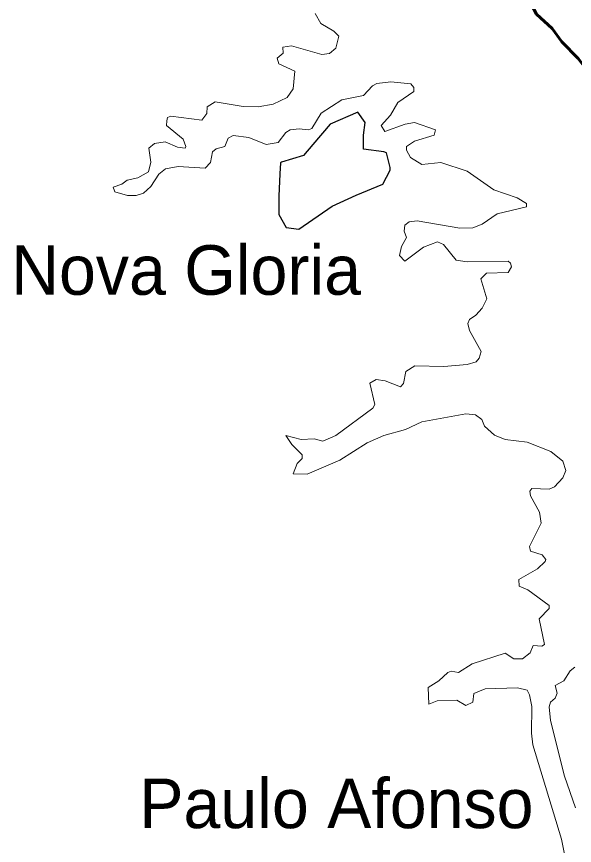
# Model space of a CAD drawing. Extents: x 553962 to 842807, y 8883888 to 9032388.
# Drawn here: x 578481 to 584109, y 8960294 to 8968659 of the extents above; entities that cross this region are included whole.
import ezdxf
from ezdxf.enums import TextEntityAlignment as Align

# ---------------------------------------------------------------- set-up
doc = ezdxf.new("R2010")
doc.units = 0
doc.header["$LTSCALE"] = 200
doc.linetypes.add('LONG_DASH_SHORT_DASH', pattern=[9.9, 6, -1.2, 1.5, -1.2])
for name, color, linetype, lineweight in [('21', 7, 'Continuous', 25), ('25', 7, 'Continuous', 13), ('41', 7, 'Continuous', 40), ('7', 7, 'LONG_DASH_SHORT_DASH', 60)]:
    doc.layers.add(name, color=color, linetype=linetype, lineweight=lineweight)

msp = doc.modelspace()

# ---------------------------------------------------------------- linework, layer by layer
at = {"layer": '21'}
msp.add_lwpolyline([(581144.7, 8967182.6), (581135.4, 8967071.1), (581126.2, 8966848.2), (581126.2, 8966662.4), (581200.4, 8966532.3), (581330.4, 8966513.8), (581664.7, 8966746), (581906.1, 8966857.5), (582175.4, 8966968.9), (582249.7, 8967108.2), (582249.7, 8967136.1), (582212.6, 8967284.7), (582184.7, 8967294), (581980.4, 8967321.9), (581980.4, 8967461.2), (581999, 8967591.2), (581924.7, 8967693.4), (581646.1, 8967572.7), (581469.7, 8967368.3), (581376.9, 8967256.9), (581154, 8967191.8)], close=True, dxfattribs=at)
at = {"layer": '25'}
msp.add_line((579471.8, 8966890.6), (579467.6, 8966902.2), dxfattribs=at)
msp.add_line((579471.8, 8966890.6), (579467.6, 8966902.2), dxfattribs=at)
for points in [[(579997.9, 8967607), (580002.2, 8967641.4), (580036, 8967653.3), (580349.3, 8967615), (580399.9, 8967680.5), (580404.5, 8967748.8), (580485.3, 8967797.5), (580765.4, 8967750.9), (580918.4, 8967748.8), (581071.3, 8967774.2), (581209.4, 8967844.3), (581273.1, 8967931.4), (581290, 8968109.6), (581126.5, 8968182.3), (581109.5, 8968238.9), (581170.9, 8968290.2), (581167, 8968349.8), (581254, 8968362.6), (581560.2, 8968277.7), (581636.5, 8968288.5), (581702.2, 8968341.5), (581733.9, 8968462.6), (581683.1, 8968511.3), (581551.5, 8968590), (581492, 8968691.9)], [(579997.9, 8967607), (580002.2, 8967641.4), (580036, 8967653.3), (580349.3, 8967615), (580399.9, 8967680.5), (580404.5, 8967748.8), (580485.3, 8967797.5), (580765.4, 8967750.9), (580918.4, 8967748.8), (581071.3, 8967774.2), (581209.4, 8967844.3), (581273.1, 8967931.4), (581290, 8968109.6), (581126.5, 8968182.3), (581109.5, 8968238.9), (581170.9, 8968290.2), (581167, 8968349.8), (581254, 8968362.6), (581560.2, 8968277.7), (581636.5, 8968288.5), (581702.2, 8968341.5), (581733.9, 8968462.6), (581683.1, 8968511.3), (581551.5, 8968590), (581492, 8968691.9)], [(581209.9, 8964412.9), (581198.1, 8964430.9), (581351.7, 8964392.4), (581483.4, 8964396.6), (581572.4, 8964375.4), (581702.2, 8964430.7), (582073.9, 8964708.9), (582095.1, 8964745.1), (582044.3, 8964959.3), (582107.7, 8964995.5), (582107.7, 8964995.5), (582201.2, 8964983), (582356.2, 8964921.4), (582384.1, 8964957.7), (582407.6, 8965076.4), (582498.3, 8965133.6), (582792, 8965127.4), (583025.6, 8965146.5), (583119.2, 8965176.5), (583148.8, 8965212.4), (583170, 8965280.6), (583051.2, 8965492.5), (583034.2, 8965562.9), (583049.1, 8965601.1), (583114.8, 8965645.7), (583178, 8965717.2), (583225.2, 8965811.2), (583165.9, 8966013.2), (583223.5, 8966068.5), (583441.9, 8966077), (583475.9, 8966134.3), (583465.2, 8966170.4), (583439.6, 8966189.4), (583025.6, 8966183.2), (582915.7, 8966200), (582789.8, 8966359.4), (582728.2, 8966384.9), (582588.1, 8966331.8), (582396.7, 8966191.8), (582346, 8966247.1), (582364.9, 8966338), (582415.8, 8966429.6), (582390.2, 8966492.9), (582396.9, 8966552.7), (582441.5, 8966588.8), (582524.1, 8966597.4), (582953.4, 8966525.2), (583085.1, 8966527.3), (583178.8, 8966563.5), (583331.5, 8966667.5), (583624.5, 8966739.8), (583624.6, 8966771.3), (583531.2, 8966831), (583297.3, 8966909.8), (583025.6, 8967098.7), (582760.3, 8967185.7), (582571.1, 8967166.8), (582456.7, 8967236.5), (582416, 8967311.4), (582416.1, 8967347.1), (582494.8, 8967400.4), (582694, 8967461.9), (582706.9, 8967517.1), (582494.3, 8967589.4), (582401.1, 8967574.5), (582195.1, 8967498.2), (582159.1, 8967561.8), (582254.4, 8967663.6), (582326.8, 8967791.2), (582488.1, 8967904.1), (582488.1, 8967944.1), (582458.3, 8967980.2), (582256.4, 8967999.4), (582116.5, 8967984.5), (582071.9, 8967959), (581982.3, 8967861.3), (581763.8, 8967818.8), (581553.6, 8967684.9), (581459.8, 8967529.9), (581427.3, 8967517.2), (581332, 8967527.8), (581241.1, 8967517), (581198.8, 8967489.5), (581119.9, 8967389.7), (580998.9, 8967368.6), (580825.2, 8967438.5), (580667.5, 8967459.7), (580614.4, 8967431.8), (580582.4, 8967349.3), (580493.6, 8967323.8), (580457.7, 8967294.3), (580438.2, 8967185.8), (580385.3, 8967130.7), (580111.4, 8967147.6), (579983.5, 8967124), (579915.9, 8967069.1), (579835, 8966943.6), (579762.8, 8966875.7), (579686.3, 8966854.5), (579601.1, 8966852.3), (579471.8, 8966890.6)], [(581209.9, 8964412.9), (581198.1, 8964430.9), (581351.7, 8964392.4), (581483.4, 8964396.6), (581572.4, 8964375.4), (581702.2, 8964430.7), (582073.9, 8964708.9), (582095.1, 8964745.1), (582044.3, 8964959.3), (582107.7, 8964995.5), (582107.7, 8964995.5), (582201.2, 8964983), (582356.2, 8964921.4), (582384.1, 8964957.7), (582407.6, 8965076.4), (582498.3, 8965133.6), (582792, 8965127.4), (583025.6, 8965146.5), (583119.2, 8965176.5), (583148.8, 8965212.4), (583170, 8965280.6), (583051.2, 8965492.5), (583034.2, 8965562.9), (583049.1, 8965601.1), (583114.8, 8965645.7), (583178, 8965717.2), (583225.2, 8965811.2), (583165.9, 8966013.2), (583223.5, 8966068.5), (583441.9, 8966077), (583475.9, 8966134.3), (583465.2, 8966170.4), (583439.6, 8966189.4), (583025.6, 8966183.2), (582915.7, 8966200), (582789.8, 8966359.4), (582728.2, 8966384.9), (582588.1, 8966331.8), (582396.7, 8966191.8), (582346, 8966247.1), (582364.9, 8966338), (582415.8, 8966429.6), (582390.2, 8966492.9), (582396.9, 8966552.7), (582441.5, 8966588.8), (582524.1, 8966597.4), (582953.4, 8966525.2), (583085.1, 8966527.3), (583178.8, 8966563.5), (583331.5, 8966667.5), (583624.5, 8966739.8), (583624.6, 8966771.3), (583531.2, 8966831), (583297.3, 8966909.8), (583025.6, 8967098.7), (582760.3, 8967185.7), (582571.1, 8967166.8), (582456.7, 8967236.5), (582416, 8967311.4), (582416.1, 8967347.1), (582494.8, 8967400.4), (582694, 8967461.9), (582706.9, 8967517.1), (582494.3, 8967589.4), (582401.1, 8967574.5), (582195.1, 8967498.2), (582159.1, 8967561.8), (582254.4, 8967663.6), (582326.8, 8967791.2), (582488.1, 8967904.1), (582488.1, 8967944.1), (582458.3, 8967980.2), (582256.4, 8967999.4), (582116.5, 8967984.5), (582071.9, 8967959), (581982.3, 8967861.3), (581763.8, 8967818.8), (581553.6, 8967684.9), (581459.8, 8967529.9), (581427.3, 8967517.2), (581332, 8967527.8), (581241.1, 8967517), (581198.8, 8967489.5), (581119.9, 8967389.7), (580998.9, 8967368.6), (580825.2, 8967438.5), (580667.5, 8967459.7), (580614.4, 8967431.8), (580582.4, 8967349.3), (580493.6, 8967323.8), (580457.7, 8967294.3), (580438.2, 8967185.8), (580385.3, 8967130.7), (580111.4, 8967147.6), (579983.5, 8967124), (579915.9, 8967069.1), (579835, 8966943.6), (579762.8, 8966875.7), (579686.3, 8966854.5), (579601.1, 8966852.3), (579471.8, 8966890.6)], [(579467.6, 8966902.2), (579455.3, 8966936.2), (579541.6, 8966967.5), (579595, 8967007.3), (579704, 8967033.2), (579811.7, 8967092.6), (579835, 8967188.5), (579813.9, 8967330.2), (579873.1, 8967378.9), (579979.2, 8967396.1), (580105, 8967343), (580105, 8967343), (580181.1, 8967330.4), (580187.4, 8967349.7), (580161, 8967421.7), (579992.3, 8967561.8), (579997.9, 8967607)], [(579467.6, 8966902.2), (579455.3, 8966936.2), (579541.6, 8966967.5), (579595, 8967007.3), (579704, 8967033.2), (579811.7, 8967092.6), (579835, 8967188.5), (579813.9, 8967330.2), (579873.1, 8967378.9), (579979.2, 8967396.1), (580105, 8967343), (580105, 8967343), (580181.1, 8967330.4), (580187.4, 8967349.7), (580161, 8967421.7), (579992.3, 8967561.8), (579997.9, 8967607)], [(583013.2, 8964651.5), (582571.3, 8964568.8), (582405.6, 8964492.4), (582184.7, 8964432.8), (582018.8, 8964356.3), (581742.6, 8964184.2), (581411.2, 8964039.8), (581271.6, 8964044.5), (581311.5, 8964150.2), (581362.2, 8964201), (581362.3, 8964235), (581258.4, 8964339.1), (581209.9, 8964412.9)], [(583013.2, 8964651.5), (582571.3, 8964568.8), (582405.6, 8964492.4), (582184.7, 8964432.8), (582018.8, 8964356.3), (581742.6, 8964184.2), (581411.2, 8964039.8), (581271.6, 8964044.5), (581311.5, 8964150.2), (581362.2, 8964201), (581362.3, 8964235), (581258.4, 8964339.1), (581209.9, 8964412.9)], [(584055.9, 8959969.5), (583979.3, 8960356.6), (583690.5, 8961308.2), (583675.7, 8961427), (583679.9, 8961694.8), (583656.7, 8961812.9), (583631.9, 8961861.4), (583535.2, 8961883.6), (583208.6, 8961873.1), (583093.8, 8961826.3), (583082.9, 8961741.4), (583013.1, 8961707.5), (582923.6, 8961760.4), (582724.2, 8961752), (582642.1, 8961718.4), (582632.6, 8961889.8), (582741.2, 8961953.9), (582832.4, 8962038.7), (582866.3, 8962051.4), (582940.9, 8962038.9), (583076.4, 8962125.7), (583410.3, 8962234), (583497.2, 8962176.9), (583584.3, 8962176.9), (583662.8, 8962238.5), (583692.8, 8962310.5), (583781.6, 8962306.4), (583807.2, 8962323.5), (583752.2, 8962580.2), (583853.2, 8962685.6), (583854, 8962716.3), (583639.8, 8962873.4), (583552.7, 8962911.8), (583548.2, 8962977.4), (583737.5, 8963086.2), (583815.2, 8963159.7), (583820, 8963181), (583784.2, 8963226), (583667.3, 8963264.5), (583654.7, 8963312.4), (583773.3, 8963547.2), (583756.3, 8963657.4), (583667.3, 8963822.9), (583661, 8963870), (583680, 8963897.4), (583854.1, 8963889), (583909.5, 8963912.6), (583992, 8964005.7), (584023.8, 8964077.5), (583992.3, 8964171.2), (583871.3, 8964269), (583632.9, 8964364.8), (583412.2, 8964392.4), (583302.1, 8964434.8), (583202.2, 8964526), (583174.1, 8964592.2), (583110.6, 8964638.7), (583013.2, 8964651.5)], [(584055.9, 8959969.5), (583979.3, 8960356.6), (583690.5, 8961308.2), (583675.7, 8961427), (583679.9, 8961694.8), (583656.7, 8961812.9), (583631.9, 8961861.4), (583535.2, 8961883.6), (583208.6, 8961873.1), (583093.8, 8961826.3), (583082.9, 8961741.4), (583013.1, 8961707.5), (582923.6, 8961760.4), (582724.2, 8961752), (582642.1, 8961718.4), (582632.6, 8961889.8), (582741.2, 8961953.9), (582832.4, 8962038.7), (582866.3, 8962051.4), (582940.9, 8962038.9), (583076.4, 8962125.7), (583410.3, 8962234), (583497.2, 8962176.9), (583584.3, 8962176.9), (583662.8, 8962238.5), (583692.8, 8962310.5), (583781.6, 8962306.4), (583807.2, 8962323.5), (583752.2, 8962580.2), (583853.2, 8962685.6), (583854, 8962716.3), (583639.8, 8962873.4), (583552.7, 8962911.8), (583548.2, 8962977.4), (583737.5, 8963086.2), (583815.2, 8963159.7), (583820, 8963181), (583784.2, 8963226), (583667.3, 8963264.5), (583654.7, 8963312.4), (583773.3, 8963547.2), (583756.3, 8963657.4), (583667.3, 8963822.9), (583661, 8963870), (583680, 8963897.4), (583854.1, 8963889), (583909.5, 8963912.6), (583992, 8964005.7), (584023.8, 8964077.5), (583992.3, 8964171.2), (583871.3, 8964269), (583632.9, 8964364.8), (583412.2, 8964392.4), (583302.1, 8964434.8), (583202.2, 8964526), (583174.1, 8964592.2), (583110.6, 8964638.7), (583013.2, 8964651.5)], [(584113.2, 8962091.9), (584066.4, 8962055.5), (584002.7, 8961956), (583913.8, 8961907.2), (583936.8, 8961830.6), (583913.5, 8961781.7), (583866.6, 8961740.8), (583856.2, 8961694.6), (583869, 8961554.4), (584009.2, 8960993.4), (584121.2, 8960674.7)], [(584113.2, 8962091.9), (584066.4, 8962055.5), (584002.7, 8961956), (583913.8, 8961907.2), (583936.8, 8961830.6), (583913.5, 8961781.7), (583866.6, 8961740.8), (583856.2, 8961694.6), (583869, 8961554.4), (584009.2, 8960993.4), (584121.2, 8960674.7)]]:
    msp.add_lwpolyline(points, dxfattribs=at)
at = {"layer": '7'}
msp.add_lwpolyline([(583174.4, 8969966), (583327.9, 8969505.4), (583474.7, 8969160.4), (583725.5, 8968684.8), (583883.2, 8968539.9), (583982.9, 8968403.5), (584146.9, 8968235.1), (584624.8, 8967616.6), (584992.2, 8967072.1), (585186.8, 8966825.7), (585377.2, 8966655.9), (585748.8, 8966438.6), (585960.5, 8966257.3), (586351.6, 8965976.8), (586551, 8965796.4), (587006.6, 8965310.9), (587303.1, 8964815.2), (587426.7, 8964495.3)], dxfattribs=at)

# ---------------------------------------------------------------- texts
at = {"layer": '41'}
for s, p in [('Nova Gloria', (580191.1, 8965851.8)), ('Paulo Afonso', (581707.6, 8960468.8))]:
    msp.add_text(s, height=500, dxfattribs=at).set_placement(p, align=Align.CENTER)

doc.saveas('drawing.dxf')
